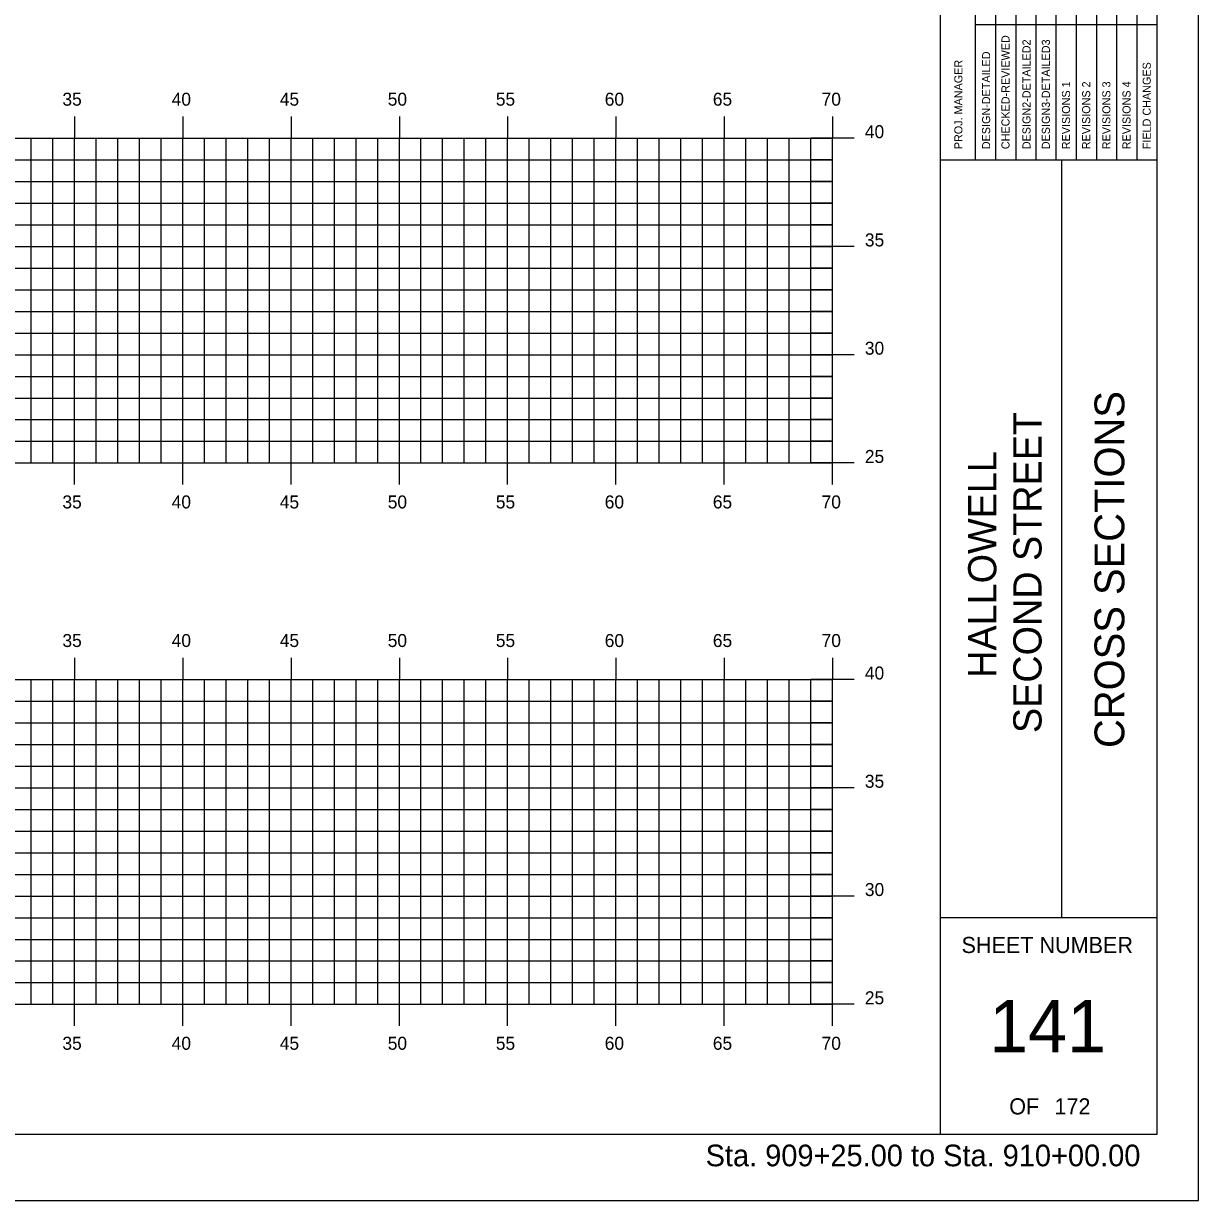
# Model space of a CAD drawing. Extents: x 1026799 to 1026969, y 394697 to 394807.
# Drawn here: x 1026915 to 1026969.3, y 394696.5 to 394750.9 of the extents above; entities that cross this region are included whole.
import ezdxf

# ---------------------------------------------------------------- set-up
doc = ezdxf.new("R2010")
doc.units = 0
for name, color, linetype in [('BORDER', 7, 'Continuous'), ('H_V ANNOTATION', 7, 'Continuous'), ('HIGHWAY_TITLE', 7, 'Continuous'), ('MAJOR', 7, 'Continuous'), ('MINOR', 7, 'Continuous'), ('PLOT BOUNDARY', 7, 'Continuous')]:
    doc.layers.add(name, color=color, linetype=linetype)

msp = doc.modelspace()

# ---------------------------------------------------------------- linework, layer by layer
at = {"layer": 'BORDER'}
for p, q in [((1026957.348, 394699.607), (1026957.348, 394804.61)), ((1026967.348, 394699.607), (1026967.348, 394804.607)), ((1026957.348, 394744.61), (1026967.348, 394744.61)), ((1026962.939, 394709.61), (1026962.939, 394744.61)), ((1026957.348, 394709.61), (1026967.348, 394709.61)), ((1026807.348, 394699.607), (1026967.348, 394699.607))]:
    msp.add_line(p, q, dxfattribs=at)
for points in [[(1026959.895, 394744.613), (1026959.895, 394762.11)], [(1026960.827, 394762.11), (1026960.827, 394744.613)], [(1026961.759, 394744.613), (1026961.759, 394762.11)], [(1026962.69, 394744.613), (1026962.69, 394762.11)], [(1026963.622, 394744.613), (1026963.622, 394762.11)], [(1026964.554, 394744.613), (1026964.554, 394762.11)], [(1026965.485, 394744.613), (1026965.485, 394762.11)], [(1026966.417, 394744.613), (1026966.417, 394762.11)], [(1026958.964, 394744.613), (1026958.964, 394761.404)], [(1026958.963, 394750.86), (1026967.348, 394750.86)]]:
    msp.add_lwpolyline(points, dxfattribs=at)
at = {"layer": 'MAJOR'}
for p, q in [((1026917.348, 394746.609), (1026917.348, 394745.607)), ((1026922.348, 394746.609), (1026922.348, 394745.607)), ((1026927.348, 394746.609), (1026927.348, 394745.607)), ((1026932.348, 394746.609), (1026932.348, 394745.607)), ((1026937.348, 394746.609), (1026937.348, 394745.607)), ((1026942.348, 394746.609), (1026942.348, 394745.607)), ((1026947.348, 394746.609), (1026947.348, 394745.607)), ((1026952.348, 394746.609), (1026952.348, 394745.607)), ((1026812.348, 394745.607), (1026952.348, 394745.607)), ((1026917.348, 394730.607), (1026917.348, 394745.607)), ((1026922.348, 394730.607), (1026922.348, 394745.607)), ((1026927.348, 394730.607), (1026927.348, 394745.607)), ((1026932.348, 394730.607), (1026932.348, 394745.607)), ((1026937.348, 394730.607), (1026937.348, 394745.607)), ((1026942.348, 394730.607), (1026942.348, 394745.607)), ((1026947.348, 394730.607), (1026947.348, 394745.607)), ((1026953.35, 394745.607), (1026951.346, 394745.607)), ((1026952.348, 394730.607), (1026952.348, 394745.607)), ((1026812.348, 394740.607), (1026952.348, 394740.607)), ((1026953.35, 394740.607), (1026951.346, 394740.607)), ((1026812.348, 394735.607), (1026952.348, 394735.607)), ((1026953.35, 394735.607), (1026951.346, 394735.607)), ((1026812.348, 394730.607), (1026952.348, 394730.607)), ((1026917.348, 394729.605), (1026917.348, 394730.607)), ((1026922.348, 394729.605), (1026922.348, 394730.607)), ((1026927.348, 394729.605), (1026927.348, 394730.607)), ((1026932.348, 394729.605), (1026932.348, 394730.607)), ((1026937.348, 394729.605), (1026937.348, 394730.607)), ((1026942.348, 394729.605), (1026942.348, 394730.607)), ((1026947.348, 394729.605), (1026947.348, 394730.607)), ((1026953.35, 394730.607), (1026951.346, 394730.607)), ((1026952.348, 394729.605), (1026952.348, 394730.607)), ((1026917.348, 394721.609), (1026917.348, 394720.607)), ((1026922.348, 394721.609), (1026922.348, 394720.607)), ((1026927.348, 394721.609), (1026927.348, 394720.607)), ((1026932.348, 394721.609), (1026932.348, 394720.607)), ((1026937.348, 394721.609), (1026937.348, 394720.607)), ((1026942.348, 394721.609), (1026942.348, 394720.607)), ((1026947.348, 394721.609), (1026947.348, 394720.607)), ((1026952.348, 394721.609), (1026952.348, 394720.607)), ((1026812.348, 394720.607), (1026952.348, 394720.607)), ((1026917.348, 394705.607), (1026917.348, 394720.607)), ((1026922.348, 394705.607), (1026922.348, 394720.607)), ((1026927.348, 394705.607), (1026927.348, 394720.607)), ((1026932.348, 394705.607), (1026932.348, 394720.607)), ((1026937.348, 394705.607), (1026937.348, 394720.607)), ((1026942.348, 394705.607), (1026942.348, 394720.607)), ((1026947.348, 394705.607), (1026947.348, 394720.607)), ((1026953.35, 394720.607), (1026951.346, 394720.607)), ((1026952.348, 394705.607), (1026952.348, 394720.607)), ((1026812.348, 394715.607), (1026952.348, 394715.607)), ((1026953.35, 394715.607), (1026951.346, 394715.607)), ((1026812.348, 394710.607), (1026952.348, 394710.607)), ((1026953.35, 394710.607), (1026951.346, 394710.607)), ((1026812.348, 394705.607), (1026952.348, 394705.607)), ((1026917.348, 394704.605), (1026917.348, 394705.607)), ((1026922.348, 394704.605), (1026922.348, 394705.607)), ((1026927.348, 394704.605), (1026927.348, 394705.607)), ((1026932.348, 394704.605), (1026932.348, 394705.607)), ((1026937.348, 394704.605), (1026937.348, 394705.607)), ((1026942.348, 394704.605), (1026942.348, 394705.607)), ((1026947.348, 394704.605), (1026947.348, 394705.607)), ((1026953.35, 394705.607), (1026951.346, 394705.607)), ((1026952.348, 394704.605), (1026952.348, 394705.607))]:
    msp.add_line(p, q, dxfattribs=at)
at = {"layer": 'MINOR'}
for p, q in [((1026915.348, 394730.607), (1026915.348, 394745.607)), ((1026916.348, 394730.607), (1026916.348, 394745.607)), ((1026918.348, 394730.607), (1026918.348, 394745.607)), ((1026919.348, 394730.607), (1026919.348, 394745.607)), ((1026920.348, 394730.607), (1026920.348, 394745.607)), ((1026921.348, 394730.607), (1026921.348, 394745.607)), ((1026923.348, 394730.607), (1026923.348, 394745.607)), ((1026924.348, 394730.607), (1026924.348, 394745.607)), ((1026925.348, 394730.607), (1026925.348, 394745.607)), ((1026926.348, 394730.607), (1026926.348, 394745.607)), ((1026928.348, 394730.607), (1026928.348, 394745.607)), ((1026929.348, 394730.607), (1026929.348, 394745.607)), ((1026930.348, 394730.607), (1026930.348, 394745.607)), ((1026931.348, 394730.607), (1026931.348, 394745.607)), ((1026933.348, 394730.607), (1026933.348, 394745.607)), ((1026934.348, 394730.607), (1026934.348, 394745.607)), ((1026935.348, 394730.607), (1026935.348, 394745.607)), ((1026936.348, 394730.607), (1026936.348, 394745.607)), ((1026938.348, 394730.607), (1026938.348, 394745.607)), ((1026939.348, 394730.607), (1026939.348, 394745.607)), ((1026940.348, 394730.607), (1026940.348, 394745.607)), ((1026941.348, 394730.607), (1026941.348, 394745.607)), ((1026943.348, 394730.607), (1026943.348, 394745.607)), ((1026944.348, 394730.607), (1026944.348, 394745.607)), ((1026945.348, 394730.607), (1026945.348, 394745.607)), ((1026946.348, 394730.607), (1026946.348, 394745.607)), ((1026948.348, 394730.607), (1026948.348, 394745.607)), ((1026949.348, 394730.607), (1026949.348, 394745.607)), ((1026950.348, 394730.607), (1026950.348, 394745.607)), ((1026951.348, 394730.607), (1026951.348, 394745.607)), ((1026812.348, 394744.607), (1026952.348, 394744.607)), ((1026952.348, 394744.607), (1026951.346, 394744.607)), ((1026812.348, 394743.607), (1026952.348, 394743.607)), ((1026952.348, 394743.607), (1026951.346, 394743.607)), ((1026812.348, 394742.607), (1026952.348, 394742.607)), ((1026952.348, 394742.607), (1026951.346, 394742.607)), ((1026812.348, 394741.607), (1026952.348, 394741.607)), ((1026952.348, 394741.607), (1026951.346, 394741.607)), ((1026812.348, 394739.607), (1026952.348, 394739.607)), ((1026952.348, 394739.607), (1026951.346, 394739.607)), ((1026812.348, 394738.607), (1026952.348, 394738.607)), ((1026952.348, 394738.607), (1026951.346, 394738.607)), ((1026812.348, 394737.607), (1026952.348, 394737.607)), ((1026952.348, 394737.607), (1026951.346, 394737.607)), ((1026812.348, 394736.607), (1026952.348, 394736.607)), ((1026952.348, 394736.607), (1026951.346, 394736.607)), ((1026812.348, 394734.607), (1026952.348, 394734.607)), ((1026952.348, 394734.607), (1026951.346, 394734.607)), ((1026812.348, 394733.607), (1026952.348, 394733.607)), ((1026952.348, 394733.607), (1026951.346, 394733.607)), ((1026812.348, 394732.607), (1026952.348, 394732.607)), ((1026952.348, 394732.607), (1026951.346, 394732.607)), ((1026812.348, 394731.607), (1026952.348, 394731.607)), ((1026952.348, 394731.607), (1026951.346, 394731.607)), ((1026915.348, 394705.607), (1026915.348, 394720.607)), ((1026916.348, 394705.607), (1026916.348, 394720.607)), ((1026918.348, 394705.607), (1026918.348, 394720.607)), ((1026919.348, 394705.607), (1026919.348, 394720.607)), ((1026920.348, 394705.607), (1026920.348, 394720.607)), ((1026921.348, 394705.607), (1026921.348, 394720.607)), ((1026923.348, 394705.607), (1026923.348, 394720.607)), ((1026924.348, 394705.607), (1026924.348, 394720.607)), ((1026925.348, 394705.607), (1026925.348, 394720.607)), ((1026926.348, 394705.607), (1026926.348, 394720.607)), ((1026928.348, 394705.607), (1026928.348, 394720.607)), ((1026929.348, 394705.607), (1026929.348, 394720.607)), ((1026930.348, 394705.607), (1026930.348, 394720.607)), ((1026931.348, 394705.607), (1026931.348, 394720.607)), ((1026933.348, 394705.607), (1026933.348, 394720.607)), ((1026934.348, 394705.607), (1026934.348, 394720.607)), ((1026935.348, 394705.607), (1026935.348, 394720.607)), ((1026936.348, 394705.607), (1026936.348, 394720.607)), ((1026938.348, 394705.607), (1026938.348, 394720.607)), ((1026939.348, 394705.607), (1026939.348, 394720.607)), ((1026940.348, 394705.607), (1026940.348, 394720.607)), ((1026941.348, 394705.607), (1026941.348, 394720.607)), ((1026943.348, 394705.607), (1026943.348, 394720.607)), ((1026944.348, 394705.607), (1026944.348, 394720.607)), ((1026945.348, 394705.607), (1026945.348, 394720.607)), ((1026946.348, 394705.607), (1026946.348, 394720.607)), ((1026948.348, 394705.607), (1026948.348, 394720.607)), ((1026949.348, 394705.607), (1026949.348, 394720.607)), ((1026950.348, 394705.607), (1026950.348, 394720.607)), ((1026951.348, 394705.607), (1026951.348, 394720.607)), ((1026812.348, 394719.607), (1026952.348, 394719.607)), ((1026952.348, 394719.607), (1026951.346, 394719.607)), ((1026812.348, 394718.607), (1026952.348, 394718.607)), ((1026952.348, 394718.607), (1026951.346, 394718.607)), ((1026812.348, 394717.607), (1026952.348, 394717.607)), ((1026952.348, 394717.607), (1026951.346, 394717.607)), ((1026812.348, 394716.607), (1026952.348, 394716.607)), ((1026952.348, 394716.607), (1026951.346, 394716.607)), ((1026812.348, 394714.607), (1026952.348, 394714.607)), ((1026952.348, 394714.607), (1026951.346, 394714.607)), ((1026812.348, 394713.607), (1026952.348, 394713.607)), ((1026952.348, 394713.607), (1026951.346, 394713.607)), ((1026812.348, 394712.607), (1026952.348, 394712.607)), ((1026952.348, 394712.607), (1026951.346, 394712.607)), ((1026812.348, 394711.607), (1026952.348, 394711.607)), ((1026952.348, 394711.607), (1026951.346, 394711.607)), ((1026812.348, 394709.607), (1026952.348, 394709.607)), ((1026952.348, 394709.607), (1026951.346, 394709.607)), ((1026812.348, 394708.607), (1026952.348, 394708.607)), ((1026952.348, 394708.607), (1026951.346, 394708.607)), ((1026812.348, 394707.607), (1026952.348, 394707.607)), ((1026952.348, 394707.607), (1026951.346, 394707.607)), ((1026812.348, 394706.607), (1026952.348, 394706.607)), ((1026952.348, 394706.607), (1026951.346, 394706.607))]:
    msp.add_line(p, q, dxfattribs=at)
at = {"layer": 'PLOT BOUNDARY'}
msp.add_lwpolyline([(1026799.254, 394696.548), (1026969.254, 394696.548), (1026969.254, 394806.548), (1026799.254, 394806.548)], close=True, dxfattribs=at)

# ---------------------------------------------------------------- texts
at = {"layer": 'BORDER'}
for s, height, rotation, p in [('CHECKED-REVIEWED', 0.37275, 90, (1026960.529, 394745.098)), ('DESIGN2-DETAILED2', 0.37275, 90, (1026961.498, 394745.098)), ('DESIGN3-DETAILED3', 0.37275, 90, (1026962.392, 394745.098)), ('DESIGN-DETAILED', 0.37275, 90, (1026959.634, 394745.098)), ('PROJ. MANAGER', 0.37275, 90, (1026958.352, 394745.098)), ('FIELD CHANGES', 0.37275, 90, (1026967.051, 394745.098)), ('REVISIONS 1', 0.37275, 90, (1026963.324, 394745.098)), ('REVISIONS 2', 0.37275, 90, (1026964.256, 394745.098)), ('REVISIONS 3', 0.37275, 90, (1026965.187, 394745.098)), ('REVISIONS 4', 0.37275, 90, (1026966.119, 394745.098)), ('CROSS SECTIONS', 1.37787, 90, (1026965.832, 394717.444)), ('SHEET NUMBER', 0.74527, 360, (1026958.313, 394707.973)), ('141', 2.4194, 360, (1026959.589, 394703.389)), ('OF', 0.7453, 360, (1026960.515, 394700.52)), ('172', 0.7453, 360, (1026962.604, 394700.52))]:
    msp.add_text(s, height=height, rotation=rotation, dxfattribs=at).set_placement(p)
at = {"layer": 'H_V ANNOTATION'}
for s, height, p in [('35', 0.6, (1026916.788, 394747.107)), ('40', 0.6, (1026921.834, 394747.107)), ('45', 0.6, (1026926.826, 394747.107)), ('50', 0.6, (1026931.812, 394747.107)), ('55', 0.6, (1026936.804, 394747.107)), ('60', 0.6, (1026941.834, 394747.107)), ('65', 0.6, (1026946.826, 394747.107)), ('70', 0.6, (1026951.85, 394747.107)), ('40', 0.6, (1026953.848, 394745.607)), ('35', 0.6, (1026953.848, 394740.607)), ('30', 0.6, (1026953.848, 394735.607)), ('25', 0.6, (1026953.848, 394730.607)), ('35', 0.6, (1026916.788, 394728.507)), ('40', 0.6, (1026921.834, 394728.507)), ('45', 0.6, (1026926.826, 394728.507)), ('50', 0.6, (1026931.812, 394728.507)), ('55', 0.6, (1026936.804, 394728.507)), ('60', 0.6, (1026941.834, 394728.507)), ('65', 0.6, (1026946.826, 394728.507)), ('70', 0.6, (1026951.85, 394728.507)), ('35', 0.6, (1026916.788, 394722.107)), ('40', 0.6, (1026921.834, 394722.107)), ('45', 0.6, (1026926.826, 394722.107)), ('50', 0.6, (1026931.812, 394722.107)), ('55', 0.6, (1026936.804, 394722.107)), ('60', 0.6, (1026941.834, 394722.107)), ('65', 0.6, (1026946.826, 394722.107)), ('70', 0.6, (1026951.85, 394722.107)), ('40', 0.6, (1026953.848, 394720.607)), ('35', 0.6, (1026953.848, 394715.607)), ('30', 0.6, (1026953.848, 394710.607)), ('25', 0.6, (1026953.848, 394705.607)), ('35', 0.6, (1026916.788, 394703.507)), ('40', 0.6, (1026921.834, 394703.507)), ('45', 0.6, (1026926.826, 394703.507)), ('50', 0.6, (1026931.812, 394703.507)), ('55', 0.6, (1026936.804, 394703.507)), ('60', 0.6, (1026941.834, 394703.507)), ('65', 0.6, (1026946.826, 394703.507)), ('70', 0.6, (1026951.85, 394703.507)), ('Sta. 909+25.00 to Sta. 910+00.00', 1.0002, (1026946.494, 394698.126))]:
    msp.add_text(s, height=height, dxfattribs=at).set_placement(p)
at = {"layer": 'HIGHWAY_TITLE'}
for s, height, p in [('SECOND STREET', 1.30428, (1026962.007, 394718.134)), ('HALLOWELL', 1.3043, (1026959.92, 394720.684))]:
    msp.add_text(s, height=height, rotation=90, dxfattribs=at).set_placement(p)

doc.saveas('drawing.dxf')
